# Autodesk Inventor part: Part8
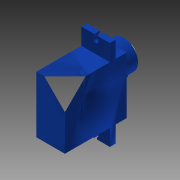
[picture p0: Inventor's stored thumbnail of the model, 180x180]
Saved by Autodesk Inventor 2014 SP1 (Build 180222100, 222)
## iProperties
Created: 2017-05
Part Number: Part8
Material: PPS Plastic
Document SubType Name: Modeling
Designer: L.Đ.P
Density: 1.637 g/cm^3
Appearance: Smooth - White
Author: L.Đ.P
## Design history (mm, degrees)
sketch "Sketch1"
  geometry: L1 (5.075, -10.1)-(-5.075, -10.1); L2 (-5.075, -10.1)-(-5.075, 10.1); L3 (-5.075, 10.1)-(5.075, 10.1); L4 (5.075, 10.1)-(5.075, -10.1); L5 (0, 0)-(0, -6.792); L6 (0, 0)-(-3.426, 0); 2 further points
  constraints: 12 end point, 3 parallel, 2 midpoint, 2 perpendicular, 2 point on line, 1 horizontal
  dimensions: "d0" = 10.15 distance of L2.end L3.end; "d1" = 20.2 distance of L1.end L2.end
extrude "Extrusion1" new body sketch "Sketch1" distance "d2" = 16; taper "d3" = 0 deg
sketch "Sketch2"
  geometry: L1 (5.075, 10.1)-(-5.075, 10.1) reference; L2 (-5.075, 10.1)-(-5.075, -10.1) reference; L3 (5.075, -10.1)-(5.075, 10.1) reference; L4 (5.075, -16)-(-5.075, -16); L5 (-5.075, -16)-(-5.075, 16); L6 (-5.075, 16)-(5.075, 16); L7 (5.075, 16)-(5.075, -16); 3 further points
  constraints: 8 end point, 4 midpoint, 2 parallel, 1 horizontal, 1 perpendicular
  dimensions: "d4" = 32 distance between parallel lines of L4 L6
extrude "Extrusion2" join sketch "Sketch2" distance "d5" = 2; taper "d6" = 0 deg
sketch "Sketch3"
  geometry: L1 (5.075, -16)-(-5.075, -16) reference; L2 (-5.075, -16)-(-5.075, 16) reference; L3 (-5.075, 16)-(5.075, 16) reference; L4 (5.075, 16)-(5.075, -16) reference; L5 (5.075, -16)-(-5.075, -16) reference; L6 (-5.075, -16)-(-5.075, 16) reference; L7 (-5.075, 16)-(5.075, 16) reference; L8 (5.075, 16)-(5.075, -16) reference; L9 (-5.075, 10.1)-(5.075, 10.1) reference; L10 (5.075, 10.1)-(5.075, -10.1) reference; L11 (5.075, -10.1)-(-5.075, -10.1) reference; L12 (-5.075, -10.1)-(-5.075, 10.1) reference; 1 further point
extrude "Extrusion3" join sketch "Sketch3" distance "d7" = 4; taper "d8" = 0 deg
sketch "Sketch4"
  geometry: L1 (-5.075, 10.1)-(-5.075, -10.1) reference; L2 (-5.075, -10.1)-(5.075, -10.1) reference; L3 (5.075, -10.1)-(5.075, 10.1) reference; C1 r 5.075 at (0, -5.025); C2 r 1.5 at (0, 0.675); 1 further point
  constraints: 3 tangent, 2 centre point
  dimensions: "d10" = 3 diameter of C2; "d11" = 5.7 distance of C1.centre C2.centre; "d12" = 5.075 distance from line of L3 C2.centre
extrude "Extrusion4" join sketch "Sketch4" distance "d13" = 4; taper "d14" = 0 deg
sketch "Sketch5"
  geometry: L1 (-5.075, -16)-(5.075, -16) reference; L2 (5.075, -16)-(5.075, -10.1) reference; L3 (0.5, -16)-(-0.5, -16); L4 (-0.5, -16)-(-0.5, -15); L5 (-0.5, -15)-(0.5, -15); L6 (0.5, -15)-(0.5, -16); C1 r 1 at (0, -14.5); 2 further points
  constraints: 8 end point, 2 midpoint, 2 parallel, 1 centre point, 1 horizontal, 1 perpendicular, 1 point on line
  dimensions: "d15" = 2 diameter of C1; "d16" = 1.5 distance from line of L1 C1.centre; "d17" = 1 distance of L4.end L5.end; "d18" = 1 distance of L3.end L4.end; "d19" = 5.075 distance from line of L2 C1.centre
extrude "Extrusion5" cut sketch "Sketch5" distance "d20" = 4; taper "d21" = 0 deg
mirror "Mirror3"
sketch "Sketch11"
  geometry: C1 r 2.5 at (0, -5.025); A1 r 5.075 centre (0, -5.025) between (-1.276, -0.113) and (1.276, -0.113) reference; 1 further point
  constraints: 1 centre point, 1 coincident
  dimensions: "d49" = 5 diameter of C1
extrude "Extrusion11" join sketch "Sketch11" distance "d50" = 2; taper "d51" = 0 deg
body "Solid1"
node "Projected Loop1"
node "Project Cut Edges1"
node "Project Cut Edges2"
